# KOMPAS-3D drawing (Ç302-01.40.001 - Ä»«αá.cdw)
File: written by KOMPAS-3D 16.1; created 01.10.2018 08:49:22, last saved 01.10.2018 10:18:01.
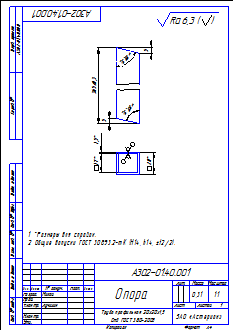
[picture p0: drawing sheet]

Sheet 1: A4, portrait

Title block, sheet 1: name: Опора; designation: А302-01.40.001; mass: 0,31; scale: 1:1; sheets: 1; organisation: ЗАО «Астерион»; sheet format: A4; stored path: \\192.168.87.28\Konstructor_doc\Мембранные насосы\Мембранный электропривод\А302-00.00.000 - ASTRA-302 (МЭ200)\3Д ПВХ\А302-01.40.001 - Опора.cdw; drawn by: Милов; technical control: Лучихин

Views: Вид 1, Слева, Проекционный вид 2
Referenced files in \\192.168.87.28\Konstructor_doc\Мембранные насосы\Мембранный электропривод\А302-00.00.000 - ASTRA-302 (МЭ200)\3Д ПВХ\Отработка\: Труба профильная 25х25х1,5-1.m3d
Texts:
  Труба профильная 20х20х1,5
  Ст3 ГОСТ 380-2005
  *Размеры для справок.
  Общие допуски ГОСТ 30893.2-mK (H14, h14,  t2/2).
  Ra 6,3
  Ra 6,3 ( )
Dimensions and other numbers on the sheet: 365±0,3; 75 58'; 5; 20; 17; 1,5; 1:1; 1; 0,31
